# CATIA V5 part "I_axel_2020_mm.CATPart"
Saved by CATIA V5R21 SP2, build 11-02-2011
Part number: Axel_2020_mm
Bounding box of the stored display mesh (mm): x -10 to 10, y -10 to 10, z 0 to 50
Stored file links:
  \\ariel.ad.iei.liu.se\LAB_DELMIA\A1_LAB_INTRO_2011\LAB_INTRO_DATA_2011\I_axel_2020_mm.CATPart
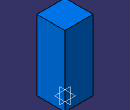
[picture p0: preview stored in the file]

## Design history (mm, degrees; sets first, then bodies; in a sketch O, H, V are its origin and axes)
Body1 (main body)
  Sketch1 on xy-plane, origin (0, 0, 0), H (1, 0, 0), V (0, 1, 0)
    line L1 (-10, -10) -> (10, -10)
    line L2 (10, -10) -> (10, 10)
    line L3 (10, 10) -> (-10, 10)
    line L4 (-10, 10) -> (-10, -10)
    horizontal: L1 H, L3 H
    vertical: L2 V, L4 V
  Pad1: profile Sketch1, direction (0, 0, 1), length 50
